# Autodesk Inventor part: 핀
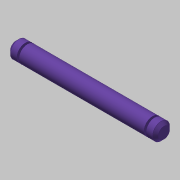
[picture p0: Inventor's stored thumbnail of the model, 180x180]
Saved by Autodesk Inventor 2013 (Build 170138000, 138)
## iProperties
Created: 2019-02
Part Number: 핀
Material: 스테인리스강
Document SubType Name: Modeling
Designer: mduedu
Density: 1 g/cm^3
Author: mduedu
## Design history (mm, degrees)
sketch "스케치1"
  geometry: L1 (-26, 0)-(26, 0); L2 (26, 0)-(26, 3); L3 (26, 3)-(-26, 3); L4 (-26, 3)-(-26, 0); L5 (-22.7, 3)-(-22, 3); L6 (-22, 3)-(-22, 2); L7 (-22, 2)-(-22.7, 2); L8 (-22.7, 2)-(-22.7, 3); L9 (0, 0)-(0, 3); L10 (22.7, 3)-(22, 3); L11 (22, 3)-(22, 2); L12 (22, 2)-(22.7, 2); L13 (22.7, 2)-(22.7, 3); 1 further point
  constraints: 26 end point, 4 parallel, 4 symmetric about line, 2 horizontal, 2 midpoint, 2 perpendicular, 1 coincident, 1 point on line
  dimensions: "d0" = 52 distance between parallel lines of L2 L4; "d2" = 6 diameter of L3 L1; "d3" = 4 diameter of L7 L1; "d4" = 44 distance between parallel lines of L11 L6; "d5" = 0.7 distance between parallel lines of L6 L8
revolve "회전1" sketch "스케치1" stored, may be unused: angle "d6" = 90 deg
chamfer "모따기1" distance "d7" = 1; stored, may be unused: second distance "d8" = 2, angle "d9" = 45 deg
node "솔리드1"
